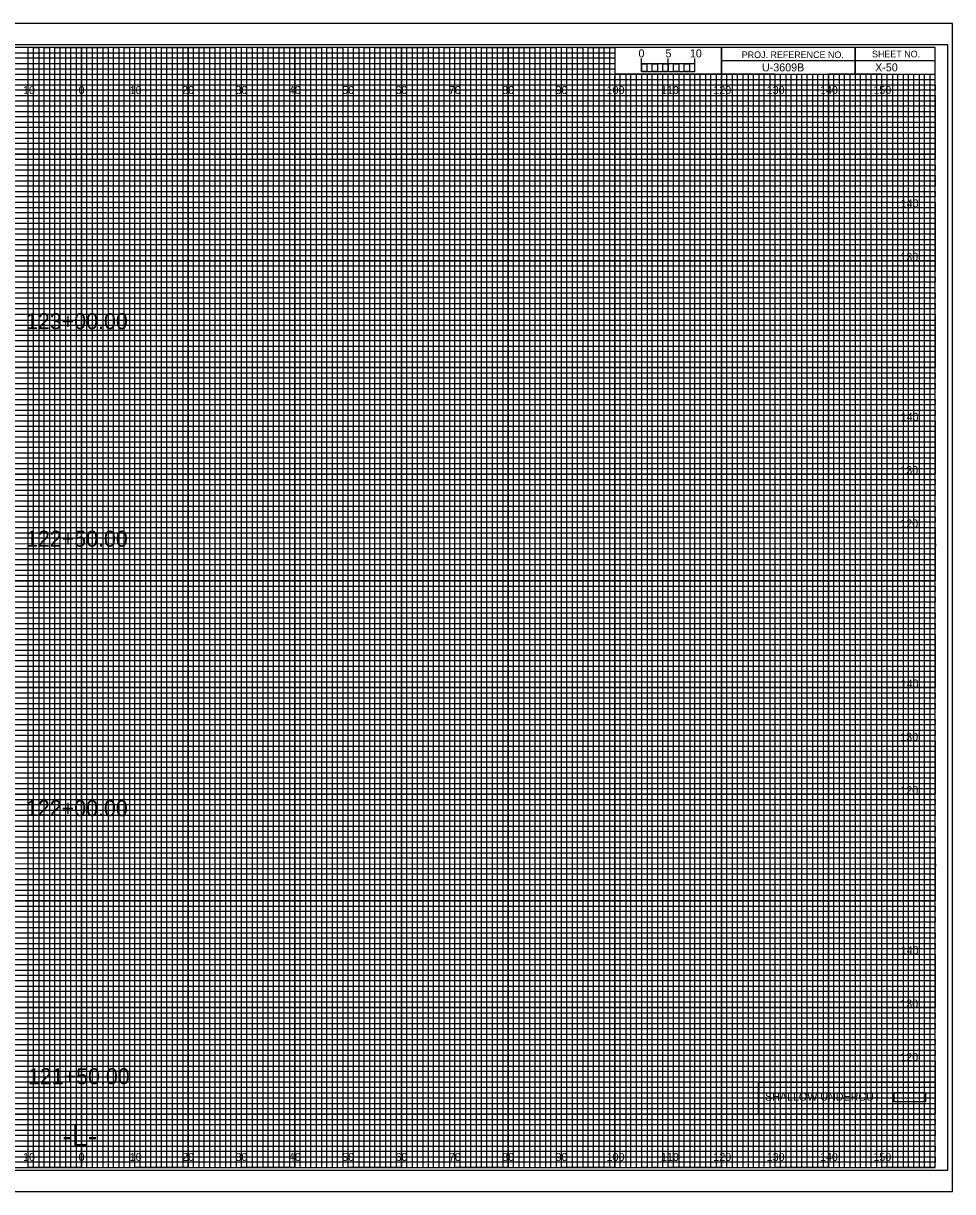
# Model space of a CAD drawing. Extents: x -13 to 329, y -17 to 10994.
# Drawn here: x 149.1 to 323.3, y 10555.5 to 10774.5 of the extents above; entities that cross this region are included whole.
import ezdxf

# ---------------------------------------------------------------- set-up
doc = ezdxf.new("R2010")
doc.units = 0
for name, color, linetype in [('Prop DSN Text', 7, 'Continuous'), ('Prop Grid Mask', 7, 'Continuous'), ('Prop Road Plan_ Recs - UC Shallow (pattern)', 7, 'Continuous'), ('Prop XS Alignment Label', 7, 'Continuous'), ('Prop XS Bar Scale Labels', 7, 'Continuous'), ('Prop XS Elevation Labels', 7, 'Continuous'), ('Prop XS Offset Labels', 7, 'Continuous'), ('Prop XS Project Number', 7, 'Continuous'), ('Prop XS Sheet Number', 7, 'Continuous'), ('Prop XS Station Labels', 7, 'Continuous'), ('Sheet Cross Section CELL', 7, 'Continuous'), ('Sheet Cross Section Grid Major CELL', 7, 'Continuous'), ('Sheet Cross Section Grid Middle CELL', 7, 'Continuous'), ('Sheet Cross Section Grid Minor 1 CELL', 7, 'Continuous'), ('Sheet Cross Section Grid Minor 2 CELL', 7, 'Continuous'), ('Sheet Cross Section Scale CELL', 7, 'Continuous'), ('Sheet Cutting Line CELL', 7, 'Continuous'), ('Sheet DOT Grid CELL', 7, 'Continuous'), ('Sheet Plot Border Inside CELL', 7, 'Continuous'), ('Sheet Plot Border Outside CELL', 7, 'Continuous')]:
    doc.layers.add(name, color=color, linetype=linetype)

msp = doc.modelspace()

# ---------------------------------------------------------------- linework, layer by layer
at = {"layer": 'Prop Grid Mask'}
msp.add_lwpolyline([(286.89, 10576.03), (320, 10576.03), (320, 10570), (286.89, 10570)], close=True, dxfattribs=at)
at = {"layer": 'Prop Road Plan_ Recs - UC Shallow (pattern)'}
msp.add_lwpolyline([(312.34, 10574.08), (318.23, 10574.08), (318.23, 10572.36), (312.34, 10572.36)], close=True, dxfattribs=at)
at = {"layer": 'Sheet Cross Section CELL'}
for p, q in [((305, 10770), (305, 10765)), ((305, 10765), (305, 10770)), ((280, 10767.5), (280, 10765)), ((320, 10767.49), (280, 10767.49)), ((280, 10765), (320, 10765))]:
    msp.add_line(p, q, dxfattribs=at)
for points in [[(320, 10770), (0, 10770), (0, 10560), (320, 10560)], [(280, 10770), (260, 10770), (260, 10765.03), (280, 10765.03)], [(320, 10770), (280, 10770), (280, 10765), (320, 10765)]]:
    msp.add_lwpolyline(points, close=True, dxfattribs=at)
at = {"layer": 'Sheet Cross Section Grid Major CELL'}
for p, q in [((150, 10770), (140, 10770)), ((150, 10560), (150, 10770)), ((170, 10770), (160, 10770)), ((160, 10770), (160, 10560)), ((170, 10560), (170, 10770)), ((190, 10770), (180, 10770)), ((180, 10770), (180, 10560)), ((190, 10560), (190, 10770)), ((210, 10770), (200, 10770)), ((200, 10770), (200, 10560)), ((210, 10560), (210, 10770)), ((230, 10770), (220, 10770)), ((220, 10770), (220, 10560)), ((230, 10560), (230, 10770)), ((250, 10770), (240, 10770)), ((240, 10770), (240, 10560)), ((250, 10560), (250, 10770)), ((260, 10770), (260, 10560)), ((270, 10560), (270, 10765)), ((290, 10765), (280, 10765)), ((280, 10765), (280, 10560)), ((290, 10560), (290, 10765)), ((310, 10765), (300, 10765)), ((300, 10765), (300, 10560)), ((310, 10560), (310, 10765)), ((160, 10560), (150, 10560)), ((180, 10560), (170, 10560)), ((200, 10560), (190, 10560)), ((220, 10560), (210, 10560)), ((240, 10560), (230, 10560)), ((260, 10560), (250, 10560)), ((280, 10560), (270, 10560)), ((300, 10560), (290, 10560)), ((320, 10560), (310, 10560)), ((320, 10560), (320, 10560))]:
    msp.add_line(p, q, dxfattribs=at)
for points in [[(0, 10760), (320, 10760), (320, 10750), (0, 10750)], [(0, 10740), (320, 10740), (320, 10730), (0, 10730)], [(0, 10720), (320, 10720), (320, 10710), (0, 10710)], [(0, 10700), (320, 10700), (320, 10690), (0, 10690)], [(0, 10680), (320, 10680), (320, 10670), (0, 10670)], [(0, 10660), (320, 10660), (320, 10650), (0, 10650)], [(0, 10640), (320, 10640), (320, 10630), (0, 10630)], [(0, 10620), (320, 10620), (320, 10610), (0, 10610)], [(0, 10600), (320, 10600), (320, 10590), (0, 10590)], [(0, 10580), (320, 10580), (320, 10570), (0, 10570)]]:
    msp.add_lwpolyline(points, dxfattribs=at)
at = {"layer": 'Sheet Cross Section Grid Middle CELL'}
for points in [[(145, 10560), (155, 10560), (155, 10770), (165, 10770), (165, 10560), (175, 10560), (175, 10770), (185, 10770), (185, 10560), (195, 10560), (195, 10770), (205, 10770), (205, 10560), (215, 10560), (215, 10770), (225, 10770), (225, 10560), (235, 10560), (235, 10770), (245, 10770), (245, 10560), (255, 10560), (255, 10770), (259.93, 10770), (260, 10770), (260, 10765), (264.99, 10765), (264.99, 10560), (275, 10560), (275, 10765), (285, 10765), (285, 10560), (295, 10560), (295, 10765), (305, 10765), (305, 10560), (315, 10560), (315, 10765)], [(0, 10765), (275, 10765)], [(0, 10745), (320, 10745), (320, 10755), (0, 10755)], [(0, 10725), (320, 10725), (320, 10735), (0, 10735)], [(0, 10705), (320, 10705), (320, 10715), (0, 10715)], [(0, 10685), (320, 10685), (320, 10695), (0, 10695)], [(0, 10665), (320, 10665), (320, 10675), (0, 10675)], [(0, 10645), (320, 10645), (320, 10655), (0, 10655)], [(0, 10625), (320, 10625), (320, 10635), (0, 10635)], [(0, 10605), (320, 10605), (320, 10615), (0, 10615)], [(0, 10585), (320, 10585), (320, 10595), (0, 10595)], [(0, 10565), (320, 10565), (320, 10575), (0, 10575)]]:
    msp.add_lwpolyline(points, dxfattribs=at)
at = {"layer": 'Sheet Cross Section Grid Minor 1 CELL'}
for p, q in [((0, 10769), (260, 10769)), ((260, 10769), (260, 10767.98)), ((260, 10767.98), (0, 10767.98)), ((0, 10767), (260, 10767)), ((260, 10767), (260, 10765.89)), ((260, 10765.89), (0, 10765.89)), ((0, 10764), (320, 10764))]:
    msp.add_line(p, q, dxfattribs=at)
for points in [[(0, 10763), (270, 10763), (320, 10763), (320, 10762), (0, 10762)], [(0, 10761), (320, 10761), (320, 10759), (0, 10759)], [(0, 10758), (320, 10758), (320, 10757), (0, 10756.98)], [(0, 10756), (320, 10756), (320, 10754), (0, 10754)], [(0, 10753), (320, 10753), (320, 10752), (0, 10752)], [(0, 10751), (320, 10751), (320, 10749), (0, 10749)], [(0, 10748), (320, 10748), (320, 10747), (0, 10747)], [(0, 10746), (320, 10746), (320, 10744), (0, 10744)], [(0, 10743), (320, 10743), (320, 10742), (0, 10742)], [(0, 10741), (320, 10741), (320, 10739), (0, 10739)], [(0, 10738), (320, 10738), (320, 10737), (0, 10737)], [(0, 10736), (320, 10736), (320, 10733.95), (320, 10733), (320, 10732), (0, 10732)], [(0, 10734), (320, 10734), (320, 10733), (0, 10733)], [(0, 10731), (320, 10731), (320, 10729), (0, 10729.03)], [(0, 10729.03), (320, 10729), (320, 10728), (0, 10728)], [(0, 10727), (320, 10727), (320, 10726), (0, 10726)], [(0, 10724), (320, 10724), (320, 10723), (0, 10723)], [(0, 10722), (320, 10722), (320, 10721), (0, 10721)], [(-0.07, 10718.89), (320, 10718.89), (320, 10717.88), (-0.07, 10717.88)], [(0, 10717), (320, 10717), (320, 10716), (0, 10716)], [(0, 10714), (320, 10714), (320, 10713), (0, 10713)], [(0, 10712), (320, 10712), (320, 10711), (0, 10711)], [(0, 10709), (320, 10709), (320, 10708), (0, 10708)], [(0, 10707), (320, 10707), (320, 10706), (0, 10706)], [(0, 10704), (320, 10704), (320, 10703), (0, 10703)], [(0, 10702), (320, 10702), (320, 10701), (0, 10701)], [(0, 10699), (320, 10699), (319.99, 10697.98), (0, 10698)], [(0, 10697), (320, 10697), (320, 10696), (0, 10696)], [(0, 10694), (320, 10694), (320, 10693), (0, 10693)], [(0, 10692), (320, 10692), (320, 10691), (0, 10691)], [(0, 10689), (320, 10689), (320, 10688), (0, 10688)], [(0, 10687), (320, 10687), (320, 10686), (0, 10686)], [(0, 10684), (320, 10684), (320, 10683), (0, 10683)], [(0, 10682), (320, 10682), (320, 10681), (0, 10681)], [(0, 10679), (320, 10679), (320, 10678), (0, 10678)], [(0, 10676.99), (320.07, 10676.91), (320, 10676), (0, 10676)], [(0, 10674), (320, 10674), (320, 10673), (0, 10673)], [(0, 10672), (320, 10672), (320, 10671), (0, 10671)], [(0, 10669), (320, 10669), (320, 10668), (0, 10668)], [(0, 10667), (320, 10667), (320, 10666), (0, 10666)], [(0, 10664), (320, 10664), (320, 10663), (0, 10663)], [(0, 10662), (320, 10662), (320, 10661), (0, 10661)], [(0, 10659), (320, 10659), (320, 10658), (0, 10658)], [(0, 10657), (320, 10657), (320, 10656), (0, 10656)], [(0, 10654), (320, 10654), (320, 10653), (0, 10653)], [(0, 10652), (320, 10652), (320, 10651), (0, 10651)], [(0, 10649), (320, 10649), (320, 10648), (0, 10648)], [(0, 10647), (320, 10647), (320, 10646), (0, 10646)], [(0, 10644), (320, 10644), (320, 10643), (0, 10643)], [(0, 10642), (320, 10642), (320, 10641), (0, 10641)], [(0, 10639), (320, 10639), (319.99, 10637.98), (0, 10638)], [(0, 10637), (320, 10637), (320, 10636), (0, 10636)], [(0, 10634), (320, 10634), (320, 10633), (0, 10633)], [(0, 10632), (320, 10632), (320, 10631), (0, 10631)], [(0, 10629), (320, 10629), (320, 10628), (0, 10628)], [(0, 10627), (320, 10627), (320, 10626), (0, 10626)], [(0, 10624), (320, 10624), (320, 10623), (0, 10623)], [(0, 10622), (320, 10622), (320, 10621), (0, 10621)], [(0, 10619), (320, 10619), (320, 10618), (0, 10618)], [(0, 10616.99), (320.07, 10616.91), (320, 10616), (0, 10616)], [(0, 10614), (320, 10614), (320, 10613), (0, 10613)], [(0, 10612), (320, 10612), (320, 10611), (0, 10611)], [(0, 10609), (320, 10609), (320, 10608), (0, 10608)], [(0, 10607), (320, 10607), (320, 10606), (0, 10606)], [(0, 10604), (320, 10604), (320, 10603), (0, 10603)], [(0, 10602), (320, 10602), (320, 10601), (0, 10601)], [(0, 10599), (320, 10599), (320, 10598), (0, 10598)], [(0, 10597), (320, 10597), (320, 10596), (0, 10596)], [(0, 10594), (320, 10594), (320, 10593), (0, 10593)], [(0, 10592), (320, 10592), (320, 10591), (0, 10591)], [(0, 10589), (320, 10589), (320, 10588), (0, 10588)], [(0, 10587), (320, 10587), (320, 10586), (0, 10586)], [(0, 10584), (320, 10584), (320, 10583), (0, 10583)], [(0, 10582), (320, 10582), (320, 10581), (0, 10581)], [(0, 10579), (320, 10579), (320, 10578), (0, 10578)], [(0, 10577), (320, 10577), (320, 10576), (0, 10576)], [(0, 10574), (320, 10574), (320, 10573), (0, 10573)], [(0, 10572), (320, 10572), (320, 10571), (0, 10571)], [(0, 10569), (320, 10569), (320, 10568), (0, 10568)], [(0, 10567), (320, 10567), (320, 10566), (0, 10566)], [(0, 10564), (320, 10564), (320, 10563), (0, 10563)], [(0, 10562), (320, 10562), (320, 10561), (0, 10561)]]:
    msp.add_lwpolyline(points, dxfattribs=at)
at = {"layer": 'Sheet Cross Section Grid Minor 2 CELL'}
for p, q in [((267, 10765), (266.01, 10765)), ((266.01, 10765), (266.01, 10560)), ((267, 10560), (267, 10765)), ((269, 10765), (268, 10765)), ((268, 10765), (268, 10560)), ((269, 10560), (269, 10765)), ((266.01, 10560), (265, 10560)), ((268, 10560), (267, 10560))]:
    msp.add_line(p, q, dxfattribs=at)
for points in [[(150, 10560), (151, 10560), (151, 10770), (152, 10770), (152, 10560)], [(152, 10560), (153, 10560), (153, 10770), (154, 10770), (154, 10560)], [(155, 10560), (156, 10560), (156, 10770), (157, 10770), (157, 10560)], [(157, 10560), (158, 10560), (158, 10770), (159, 10770), (159, 10560)], [(160, 10560), (161, 10560), (161, 10770), (162, 10770), (162, 10560)], [(162, 10560), (163, 10560), (163, 10770), (164, 10770), (164, 10560)], [(165, 10560), (166, 10560), (166, 10770), (167, 10770), (167, 10560)], [(167, 10560), (168, 10560), (168, 10770), (169, 10770), (169, 10560)], [(170, 10560), (171, 10560), (171, 10770), (172, 10770), (172, 10560)], [(172, 10560), (173, 10560), (173, 10770), (174, 10770), (174, 10560)], [(175, 10560), (176, 10560), (176, 10770), (177, 10770), (177, 10560)], [(177, 10560), (178, 10560), (178, 10770), (179, 10770), (179, 10560)], [(180, 10560), (181, 10560), (181, 10770), (182, 10770), (182, 10560)], [(182, 10560), (183, 10560), (183, 10770), (184, 10770), (184, 10560)], [(185, 10560), (186, 10560), (186, 10770), (187, 10770), (187, 10560)], [(187, 10560), (188, 10560), (188, 10770), (189, 10770), (189, 10560)], [(190, 10560), (191, 10560), (191, 10770), (192, 10770), (192, 10560)], [(192, 10560), (193, 10560), (193, 10770), (194, 10770), (194, 10560)], [(195, 10560), (196, 10560), (196, 10770), (197, 10770), (197, 10560)], [(197, 10560), (198, 10560), (198, 10770), (199, 10770), (199, 10560)], [(200, 10560), (201, 10560), (201, 10770), (202, 10770), (202, 10560)], [(202, 10560), (203, 10560), (203, 10770), (204, 10770), (204, 10560)], [(205, 10560), (206, 10560), (206, 10770), (207, 10770), (207, 10560)], [(207, 10560), (208, 10560), (208, 10770), (209, 10770), (209, 10560)], [(210, 10560), (211, 10560), (211, 10770), (212, 10770), (212, 10560)], [(212, 10560), (213, 10560), (213, 10770), (214, 10770), (214, 10560)], [(215, 10560), (216, 10560), (216, 10770), (217, 10770), (217, 10560)], [(217, 10560), (218, 10560), (218, 10770), (219, 10770), (219, 10560)], [(220, 10560), (221, 10560), (221, 10770), (222, 10770), (222, 10560)], [(222, 10560), (223, 10560), (223, 10770), (224, 10770), (224, 10560)], [(225, 10560), (226, 10560), (226, 10770), (227, 10770), (227, 10560)], [(227, 10560), (228, 10560), (228, 10770), (229, 10770), (229, 10560)], [(230, 10560), (231, 10560), (231, 10770), (232, 10770), (232, 10560)], [(232, 10560), (233, 10560), (233, 10770), (234, 10770), (234, 10560)], [(235, 10560), (236, 10560), (236, 10770), (237, 10770), (237, 10560)], [(237, 10560), (238, 10560), (238, 10770), (239, 10770), (239, 10560)], [(240, 10560), (241, 10560), (241, 10770), (242, 10770), (242, 10560)], [(242, 10560), (243, 10560), (243, 10770), (244, 10770), (244, 10560)], [(245, 10560), (246, 10560), (246, 10770), (247, 10770), (247, 10560)], [(247, 10560), (248, 10560), (248, 10770), (249, 10770), (249, 10560)], [(250, 10560), (251, 10560), (251, 10770), (252, 10770), (252, 10560)], [(252, 10560), (253, 10560), (253, 10770), (254, 10770), (254, 10560)], [(255, 10560), (256, 10560), (256, 10770), (257, 10770), (257, 10560)], [(257, 10560), (258, 10560), (258, 10770), (259, 10770), (259, 10560)], [(260, 10560), (261, 10560), (261, 10765), (262.02, 10765), (262.02, 10560)], [(262, 10560), (263, 10560), (263, 10765), (263.99, 10765), (263.99, 10560)], [(270, 10560), (270.98, 10560), (270.98, 10765), (272, 10765), (272, 10560)], [(272, 10560), (273, 10560), (273, 10765), (274.05, 10765), (274.05, 10560)], [(275, 10560), (276, 10560), (276, 10765), (277, 10765), (277, 10560)], [(277, 10560), (278, 10560), (278, 10765), (279, 10765), (279, 10560)], [(280, 10560), (281, 10560), (281, 10765), (282, 10765), (282, 10560)], [(282, 10560), (283, 10560), (283, 10765), (284, 10765), (284, 10560)], [(285, 10560), (286, 10560), (286, 10765), (287, 10765), (287, 10560)], [(287, 10560), (288, 10560), (288, 10765), (289, 10765), (289, 10560)], [(290, 10560), (291, 10560), (291, 10765), (292, 10765), (292, 10560)], [(292, 10560), (293, 10560), (293, 10765), (294, 10765), (294, 10560)], [(295, 10560), (296, 10560), (296, 10765), (297, 10765), (297, 10560)], [(297, 10560), (298, 10560), (298, 10765), (299, 10765), (299, 10560)], [(300, 10560), (301, 10560), (301, 10765), (302, 10765), (302, 10560)], [(302, 10560), (303, 10560), (303, 10765), (304, 10765), (304, 10560)], [(305, 10560), (306, 10560), (306, 10765), (307, 10765), (307, 10560)], [(307, 10560), (308, 10560), (308, 10765), (309, 10765), (309, 10560)], [(310, 10560), (311, 10560), (311, 10765), (312, 10765), (312, 10560)], [(312, 10560), (313, 10560), (313, 10765), (314, 10765), (314, 10560)], [(315, 10560), (316, 10560), (316, 10765), (317, 10765), (317, 10560)], [(317, 10560), (318, 10560), (318, 10765), (319, 10765), (319, 10560)]]:
    msp.add_lwpolyline(points, dxfattribs=at)
at = {"layer": 'Sheet Cross Section Scale CELL'}
for p, q in [((265, 10765.49), (265, 10767.9)), ((265, 10766.9), (265, 10767.9)), ((270, 10765.49), (270, 10767.9)), ((275, 10765.49), (275, 10767.9)), ((275, 10766.9), (275, 10767.9))]:
    msp.add_line(p, q, dxfattribs=at)
for points in [[(275, 10766.9), (265, 10766.9), (265, 10765.49), (275, 10765.49)], [(265, 10766.9), (266, 10766.9), (266, 10765.49), (265, 10765.49)], [(267, 10766.9), (268, 10766.9), (268, 10765.49), (267, 10765.49)], [(269, 10766.9), (270, 10766.9), (270, 10765.49), (269, 10765.49)], [(271, 10766.9), (272, 10766.9), (272, 10765.49), (271, 10765.49)], [(273, 10766.9), (274, 10766.9), (274, 10765.49), (273, 10765.49)]]:
    msp.add_lwpolyline(points, close=True, dxfattribs=at)
at = {"layer": 'Sheet Cutting Line CELL'}
for p, q in [((323.3, 10774.5), (-13.4, 10774.5)), ((-13.4, 10555.5), (323.3, 10555.5))]:
    msp.add_line(p, q, dxfattribs=at)
at = {"layer": 'Sheet DOT Grid CELL'}
for p, q in [((150, 10560), (150, 10770)), ((160, 10560), (160, 10770)), ((170, 10560), (170, 10770)), ((180, 10560), (180, 10770)), ((190, 10560), (190, 10770)), ((200, 10560), (200, 10770)), ((210, 10560), (210, 10770)), ((220, 10560), (220, 10770)), ((230, 10560), (230, 10770)), ((240, 10560), (240, 10770)), ((250, 10560), (250, 10770)), ((260, 10560), (260, 10764.69)), ((270, 10560), (270, 10764.69)), ((280, 10560), (280, 10764.69)), ((290, 10560), (290, 10764.69)), ((300, 10560), (300, 10764.69)), ((310, 10560), (310, 10764.69)), ((0, 10760), (320, 10760)), ((0, 10750), (320, 10750)), ((0, 10740), (320, 10740)), ((0, 10730), (320, 10730)), ((0, 10720), (320, 10720)), ((0, 10710), (320, 10710)), ((0, 10700), (320, 10700)), ((0, 10690), (320, 10690)), ((0, 10680), (320, 10680)), ((0, 10670), (320, 10670)), ((0, 10660), (320, 10660)), ((0, 10650), (320, 10650)), ((0, 10640), (320, 10640)), ((0, 10630), (320, 10630)), ((0, 10620), (320, 10620)), ((0, 10610), (320, 10610)), ((0, 10600), (320, 10600)), ((0, 10590), (320, 10590)), ((0, 10580), (320, 10580)), ((0, 10570), (320, 10570))]:
    msp.add_line(p, q, dxfattribs=at)
at = {"layer": 'Sheet Plot Border Inside CELL'}
msp.add_lwpolyline([(-10.8, 10559.5), (322.4, 10559.5), (322.4, 10770.5), (-10.8, 10770.5)], close=True, dxfattribs=at)
at = {"layer": 'Sheet Plot Border Outside CELL'}
msp.add_lwpolyline([(-13.4, 10555.5), (323.3, 10555.5), (323.3, 10774.5), (-13.4, 10774.5)], close=True, dxfattribs=at)

# ---------------------------------------------------------------- texts
at = {"layer": 'Prop DSN Text'}
msp.add_text('SHALLOW UNDERCUT', height=1.5, dxfattribs=at).set_placement((288.13, 10572.55))
at = {"layer": 'Prop XS Alignment Label'}
msp.add_text('-L-', height=4, dxfattribs=at).set_placement((156.42, 10564))
at = {"layer": 'Prop XS Bar Scale Labels'}
for s, p in [('5', (269.47, 10768.12)), ('10', (274.04, 10768.12))]:
    msp.add_text(s, height=1.5, dxfattribs=at).set_placement(p)
at = {"layer": 'Prop XS Elevation Labels'}
for s, p in [('140', (313.57, 10740)), ('130', (313.49, 10730)), ('140', (313.57, 10700)), ('130', (313.49, 10690)), ('120', (313.5, 10680)), ('140', (313.57, 10650)), ('130', (313.49, 10640)), ('120', (313.5, 10630)), ('140', (313.57, 10600)), ('130', (313.49, 10590)), ('120', (313.5, 10580))]:
    msp.add_text(s, height=1.5, dxfattribs=at).set_placement(p)
at = {"layer": 'Prop XS Offset Labels'}
for s, p in [('10', (149.04, 10761.25)), ('0', (159.45, 10761.25)), ('0', (159.45, 10761.25)), ('10', (169.04, 10761.25)), ('20', (178.86, 10761.25)), ('30', (188.86, 10761.25)), ('40', (198.86, 10761.25)), ('50', (208.86, 10761.25)), ('60', (218.86, 10761.25)), ('70', (228.86, 10761.25)), ('80', (238.86, 10761.25)), ('90', (248.86, 10761.25)), ('100', (258.44, 10761.25)), ('110', (268.62, 10761.25)), ('120', (278.44, 10761.25)), ('130', (288.44, 10761.25)), ('140', (298.44, 10761.25)), ('150', (308.44, 10761.25)), ('10', (149.04, 10561.25)), ('0', (159.45, 10561.25)), ('0', (159.45, 10561.25)), ('10', (169.04, 10561.25)), ('20', (178.86, 10561.25)), ('30', (188.86, 10561.25)), ('40', (198.86, 10561.25)), ('50', (208.86, 10561.25)), ('60', (218.86, 10561.25)), ('70', (228.86, 10561.25)), ('80', (238.86, 10561.25)), ('90', (248.86, 10561.25)), ('100', (258.44, 10561.25)), ('110', (268.62, 10561.25)), ('120', (278.44, 10561.25)), ('130', (288.44, 10561.25)), ('140', (298.44, 10561.25)), ('150', (308.44, 10561.25))]:
    msp.add_text(s, height=1.5, dxfattribs=at).set_placement(p)
at = {"layer": 'Prop XS Project Number'}
msp.add_text('U-3609B', height=1.5, dxfattribs=at).set_placement((287.56, 10765.5))
at = {"layer": 'Prop XS Sheet Number'}
msp.add_text('X-50', height=1.5, dxfattribs=at).set_placement((308.77, 10765.5))
at = {"layer": 'Prop XS Station Labels'}
for s, p in [('123+00.00', (149.59, 10717.18)), ('122+50.00', (149.59, 10676.4)), ('122+00.00', (149.59, 10625.89)), ('121+50.00', (149.95, 10575.63))]:
    msp.add_text(s, height=3, dxfattribs=at).set_placement(p)
at = {"layer": 'Sheet Cross Section CELL'}
for s, p in [('PROJ. REFERENCE NO.', (283.77, 10767.99)), ('SHEET NO.', (308.19, 10768.12))]:
    msp.add_text(s, height=1.25, dxfattribs=at).set_placement(p)
at = {"layer": 'Sheet Cross Section Scale CELL'}
msp.add_text('0', height=1.5, dxfattribs=at).set_placement((264.41, 10768.12))

doc.saveas('drawing.dxf')
